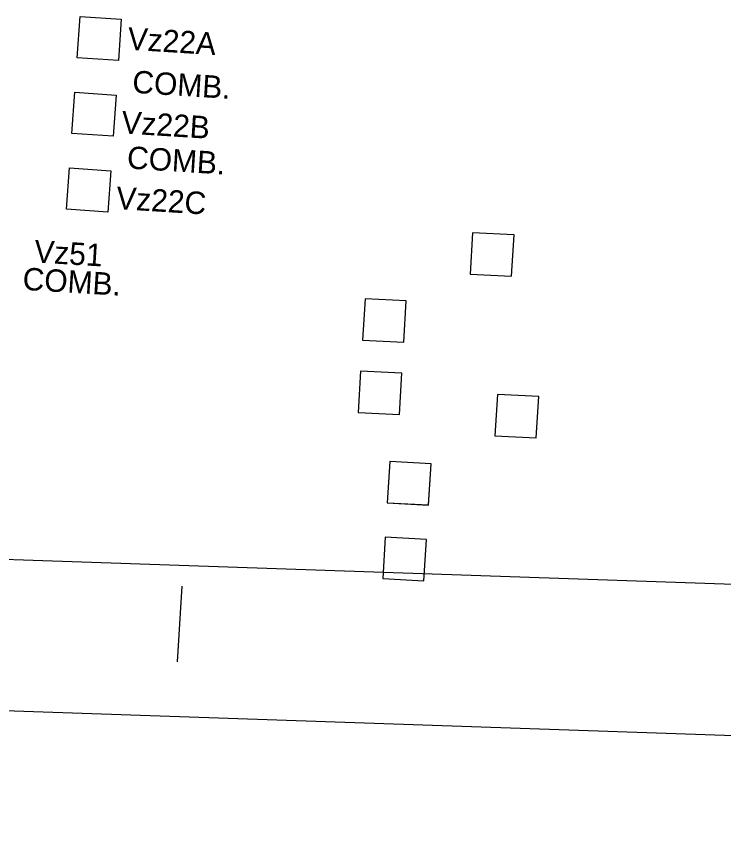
# Model space of a CAD drawing. Extents: x 647787 to 668496, y 640478 to 654412.
# Drawn here: x 661306.8 to 661409.2, y 647273.6 to 647393.1 of the extents above; entities that cross this region are included whole.
import ezdxf

# ---------------------------------------------------------------- set-up
doc = ezdxf.new("R2010")
doc.units = 0
for name, color, linetype in [('Default', 7, 'Continuous'), ('TEMP_DETECTION ZONE', 7, 'Continuous'), ('TEMP_DETECTION ZONE_STAGE 3', 7, 'Continuous'), ('TEMP_DETECTION_ZONE_STAGE 5', 7, 'Continuous'), ('TEMP_SIGNAL_POLES_STAGE 1B', 7, 'Continuous')]:
    doc.layers.add(name, color=color, linetype=linetype)

msp = doc.modelspace()

# ---------------------------------------------------------------- linework, layer by layer
at = {"layer": 'Default'}
for points in [[(662136.44, 647331.77), (661882.02, 647294.61), (661114.4, 647320.89)], [(662108.29, 647310.77), (661853.87, 647273.61), (661086.25, 647299.89)]]:
    msp.add_lwpolyline(points, dxfattribs=at)
at = {"layer": 'TEMP_DETECTION ZONE'}
for points in [[(661372.87, 647361.73), (661372.51, 647355.74), (661378.5, 647355.43), (661378.87, 647361.42)], [(661372.87, 647361.73), (661372.51, 647355.74), (661378.5, 647355.43), (661378.87, 647361.42)], [(661357.27, 647352.15), (661356.91, 647346.16), (661362.9, 647345.85), (661363.26, 647351.84)], [(661357.27, 647352.15), (661356.91, 647346.16), (661362.9, 647345.85), (661363.26, 647351.84)], [(661356.63, 647341.67), (661356.27, 647335.68), (661362.27, 647335.37), (661362.63, 647341.36)], [(661356.63, 647341.67), (661356.27, 647335.68), (661362.27, 647335.37), (661362.63, 647341.36)]]:
    msp.add_lwpolyline(points, close=True, dxfattribs=at)
at = {"layer": 'TEMP_DETECTION ZONE_STAGE 3'}
for points in [[(661376.47, 647338.28), (661376.1, 647332.29), (661382.1, 647331.98), (661382.46, 647337.97)], [(661376.47, 647338.28), (661376.1, 647332.29), (661382.1, 647331.98), (661382.46, 647337.97)], [(661376.47, 647338.28), (661376.1, 647332.29), (661382.1, 647331.98), (661382.46, 647337.97)], [(661376.47, 647338.28), (661376.11, 647332.29), (661382.1, 647331.98), (661382.46, 647337.97)], [(661360.85, 647328.56), (661360.49, 647322.57), (661366.48, 647322.26), (661366.84, 647328.24)], [(661360.85, 647328.55), (661360.49, 647322.57), (661366.48, 647322.25), (661366.84, 647328.24)], [(661360.85, 647328.55), (661360.49, 647322.57), (661366.48, 647322.25), (661366.84, 647328.24)], [(661360.85, 647328.55), (661360.49, 647322.57), (661366.48, 647322.25), (661366.84, 647328.24)], [(661360.19, 647317.58), (661359.83, 647311.59), (661365.82, 647311.28), (661366.18, 647317.26)], [(661360.19, 647317.57), (661359.83, 647311.59), (661365.82, 647311.27), (661366.18, 647317.26)], [(661360.19, 647317.57), (661359.83, 647311.59), (661365.82, 647311.27), (661366.18, 647317.26)], [(661360.19, 647317.57), (661359.83, 647311.59), (661365.82, 647311.27), (661366.18, 647317.26)]]:
    msp.add_lwpolyline(points, close=True, dxfattribs=at)
at = {"layer": 'TEMP_DETECTION_ZONE_STAGE 5'}
msp.add_line((661330.71, 647310.48), (661330.05, 647299.5), dxfattribs=at)
msp.add_line((661330.71, 647310.48), (661330.05, 647299.5), dxfattribs=at)
at = {"layer": 'TEMP_SIGNAL_POLES_STAGE 1B'}
for points in [[(661321.53, 647386.67), (661315.54, 647387.09), (661315.96, 647393.07), (661321.94, 647392.66)], [(661320.76, 647375.7), (661314.78, 647376.11), (661315.19, 647382.1), (661321.18, 647381.68)], [(661320, 647364.72), (661314.01, 647365.14), (661314.43, 647371.12), (661320.42, 647370.71)]]:
    msp.add_lwpolyline(points, close=True, dxfattribs=at)

# ---------------------------------------------------------------- texts
for s, rotation, p in [('Vz22A', 356.414, (661322.79, 647388.27)), ('COMB.', 356.414, (661323.47, 647382.01)), ('Vz22B', 356.414, (661321.89, 647376.14)), ('COMB.', 356.414, (661322.7, 647371.04)), ('Vz22C', 356.414, (661321.13, 647365.17)), ('Vz51', 356.5267, (661309.25, 647357.43)), ('COMB.', 356.5267, (661307.57, 647353.45))]:
    msp.add_text(s, height=3.25, rotation=rotation, dxfattribs=at).set_placement(p)

doc.saveas('drawing.dxf')
